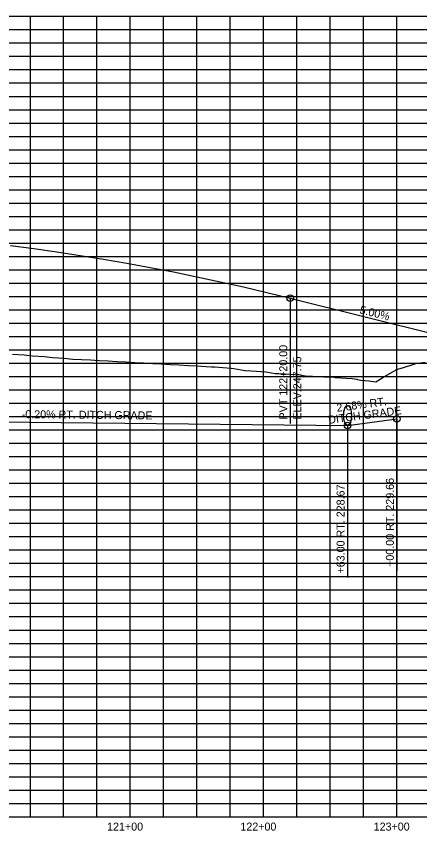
# Model space of a CAD drawing. Extents: x 921603 to 924670, y 1759276 to 1766491.
# Drawn here: x 923654 to 923957, y 1764922 to 1765532 of the extents above; entities that cross this region are included whole.
import ezdxf

# ---------------------------------------------------------------- set-up
doc = ezdxf.new("R2010")
doc.units = 0
for name, color, linetype in [('Level 8', 7, 'Continuous'), ('R_Axis_Annotation', 7, 'Continuous'), ('R_Exist Surface', 7, 'Continuous'), ('R_Grid', 7, 'Continuous'), ('R_Grid_Minor', 7, 'Continuous'), ('R_Vert Alg', 7, 'Continuous'), ('R_Vert Alg Annot', 7, 'Continuous')]:
    doc.layers.add(name, color=color, linetype=linetype)

msp = doc.modelspace()

# ---------------------------------------------------------------- linework, layer by layer
at = {"layer": 'Level 8'}
msp.add_ellipse((923902.83, 1765233.11), major_axis=(0, 7.5), ratio=0.4, dxfattribs=at)
at = {"layer": 'R_Exist Surface'}
msp.add_lwpolyline([(923651.49, 1765279.08), (923660.29, 1765278.47), (923666.55, 1765277.85), (923675.24, 1765277.26), (923681.59, 1765276.62), (923690.14, 1765276.05), (923696.6, 1765275.38), (923703.15, 1765274.99), (923709.89, 1765274.65), (923716.52, 1765274.26), (923723.19, 1765273.93), (923729.89, 1765273.53), (923736.48, 1765273.2), (923743.26, 1765272.79), (923749.77, 1765272.47), (923756.65, 1765272.05), (923763.06, 1765271.73), (923770.04, 1765271.31), (923776.35, 1765271), (923783.44, 1765270.57), (923789.64, 1765270.26), (923796.86, 1765269.82), (923800.71, 1765269.63), (923802.92, 1765269.52), (923809.14, 1765269.07), (923815.51, 1765268.59), (923817.58, 1765268.24), (923825.87, 1765266.8), (923826.02, 1765266.79), (923834.46, 1765266.26), (923841.63, 1765265.79), (923842.89, 1765265.58), (923848.62, 1765264.57), (923851.33, 1765264.43), (923859.77, 1765263.96), (923867.28, 1765263.51), (923868.2, 1765263.35), (923871.19, 1765262.8), (923876.64, 1765262.54), (923885.08, 1765262.1), (923892.45, 1765261.67), (923893.52, 1765261.46), (923893.58, 1765261.45), (923901.95, 1765261.09), (923906.31, 1765260.87), (923909.77, 1765260.28), (923910.39, 1765260.13), (923912.76, 1765259.58), (923918.83, 1765258.95), (923924.12, 1765258.36), (923927.27, 1765260.27), (923929.41, 1765261.55), (923935.7, 1765265.15), (923939.76, 1765267.44), (923943.72, 1765268.71), (923944.14, 1765268.84), (923952.58, 1765271.5), (923954.09, 1765271.97), (923961.01, 1765273.07)], dxfattribs=at)
at = {"layer": 'R_Grid'}
for p, q in [((921639.83, 1765532.26), (924639.83, 1765532.26)), ((921639.83, 1765532.26), (924639.83, 1765532.26)), ((923739.83, 1764932.26), (923739.83, 1765532.26)), ((923839.83, 1764932.26), (923839.83, 1765532.26)), ((923939.83, 1764932.26), (923939.83, 1765532.26)), ((921639.83, 1765482.26), (924639.83, 1765482.26)), ((921639.83, 1765432.26), (924639.83, 1765432.26)), ((921639.83, 1765382.26), (924639.83, 1765382.26)), ((921639.83, 1765332.26), (924639.83, 1765332.26)), ((921639.83, 1765282.26), (924639.83, 1765282.26)), ((921639.83, 1765232.26), (924639.83, 1765232.26)), ((921639.83, 1765182.26), (924639.83, 1765182.26)), ((921639.83, 1765132.26), (924639.83, 1765132.26)), ((921639.83, 1765082.26), (924639.83, 1765082.26)), ((921639.83, 1765032.26), (924639.83, 1765032.26)), ((921639.83, 1764982.26), (924639.83, 1764982.26)), ((921639.83, 1764932.26), (924639.83, 1764932.26))]:
    msp.add_line(p, q, dxfattribs=at)
at = {"layer": 'R_Grid_Minor'}
for p, q in [((923664.83, 1764932.26), (923664.83, 1765532.26)), ((923689.83, 1764932.26), (923689.83, 1765532.26)), ((923714.83, 1764932.26), (923714.83, 1765532.26)), ((923764.83, 1764932.26), (923764.83, 1765532.26)), ((923789.83, 1764932.26), (923789.83, 1765532.26)), ((923814.83, 1764932.26), (923814.83, 1765532.26)), ((923864.83, 1764932.26), (923864.83, 1765532.26)), ((923889.83, 1764932.26), (923889.83, 1765532.26)), ((923914.83, 1764932.26), (923914.83, 1765532.26)), ((921639.83, 1765522.26), (924639.83, 1765522.26)), ((921639.83, 1765512.26), (924639.83, 1765512.26)), ((921639.83, 1765502.26), (924639.83, 1765502.26)), ((921639.83, 1765492.26), (924639.83, 1765492.26)), ((921639.83, 1765472.26), (924639.83, 1765472.26)), ((921639.83, 1765462.26), (924639.83, 1765462.26)), ((921639.83, 1765452.26), (924639.83, 1765452.26)), ((921639.83, 1765442.26), (924639.83, 1765442.26)), ((921639.83, 1765422.26), (924639.83, 1765422.26)), ((921639.83, 1765412.26), (924639.83, 1765412.26)), ((921639.83, 1765402.26), (924639.83, 1765402.26)), ((921639.83, 1765392.26), (924639.83, 1765392.26)), ((921639.83, 1765372.26), (924639.83, 1765372.26)), ((921639.83, 1765362.26), (924639.83, 1765362.26)), ((921639.83, 1765352.26), (924639.83, 1765352.26)), ((921639.83, 1765342.26), (924639.83, 1765342.26)), ((921639.83, 1765322.26), (924639.83, 1765322.26)), ((921639.83, 1765312.26), (924639.83, 1765312.26)), ((921639.83, 1765302.26), (924639.83, 1765302.26)), ((921639.83, 1765292.26), (924639.83, 1765292.26)), ((921639.83, 1765272.26), (924639.83, 1765272.26)), ((921639.83, 1765262.26), (924639.83, 1765262.26)), ((921639.83, 1765252.26), (924639.83, 1765252.26)), ((921639.83, 1765242.26), (924639.83, 1765242.26)), ((921639.83, 1765222.26), (924639.83, 1765222.26)), ((921639.83, 1765212.26), (924639.83, 1765212.26)), ((921639.83, 1765202.26), (924639.83, 1765202.26)), ((921639.83, 1765192.26), (924639.83, 1765192.26)), ((921639.83, 1765172.26), (924639.83, 1765172.26)), ((921639.83, 1765162.26), (924639.83, 1765162.26)), ((921639.83, 1765152.26), (924639.83, 1765152.26)), ((921639.83, 1765142.26), (924639.83, 1765142.26)), ((921639.83, 1765122.26), (924639.83, 1765122.26)), ((921639.83, 1765112.26), (924639.83, 1765112.26)), ((921639.83, 1765102.26), (924639.83, 1765102.26)), ((921639.83, 1765092.26), (924639.83, 1765092.26)), ((921639.83, 1765072.26), (924639.83, 1765072.26)), ((921639.83, 1765062.26), (924639.83, 1765062.26)), ((921639.83, 1765052.26), (924639.83, 1765052.26)), ((921639.83, 1765042.26), (924639.83, 1765042.26)), ((921639.83, 1765022.26), (924639.83, 1765022.26)), ((921639.83, 1765012.26), (924639.83, 1765012.26)), ((921639.83, 1765002.26), (924639.83, 1765002.26)), ((921639.83, 1764992.26), (924639.83, 1764992.26)), ((921639.83, 1764972.26), (924639.83, 1764972.26)), ((921639.83, 1764962.26), (924639.83, 1764962.26)), ((921639.83, 1764952.26), (924639.83, 1764952.26)), ((921639.83, 1764942.26), (924639.83, 1764942.26))]:
    msp.add_line(p, q, dxfattribs=at)
at = {"layer": 'R_Vert Alg'}
for p, q in [((923859.83, 1765321.01), (923989.83, 1765288.51)), ((923544.83, 1765229.21), (923902.83, 1765225.61)), ((923902.83, 1765225.61), (923939.83, 1765230.56))]:
    msp.add_line(p, q, dxfattribs=at)
msp.add_lwpolyline([(923649.83, 1765360.38), (923667.33, 1765358.11), (923684.83, 1765355.64), (923702.33, 1765353), (923719.83, 1765350.18), (923737.33, 1765347.17), (923754.83, 1765343.98), (923772.33, 1765340.61), (923789.83, 1765337.05), (923807.33, 1765333.31), (923824.83, 1765329.39), (923842.33, 1765325.29), (923859.83, 1765321.01)], dxfattribs=at)
at = {"layer": 'R_Vert Alg Annot'}
for p, q in [((923859.83, 1765321.01), (923859.83, 1765311.01)), ((923859.83, 1765311.01), (923859.83, 1765227.01)), ((923939.83, 1765230.56), (923939.83, 1765200.56)), ((923902.83, 1765225.61), (923902.83, 1765195.61)), ((923902.83, 1765195.61), (923902.83, 1765111.61)), ((923939.83, 1765200.56), (923939.83, 1765116.56))]:
    msp.add_line(p, q, dxfattribs=at)
for centre in [(923859.83, 1765321.01), (923939.83, 1765230.56), (923902.83, 1765225.61)]:
    msp.add_circle(centre, 2.5, dxfattribs=at)

# ---------------------------------------------------------------- texts
at = {"layer": 'R_Axis_Annotation'}
for s, p in [('121+00', (923722.42, 1764921.91)), ('122+00', (923822.42, 1764921.91)), ('123+00', (923922.42, 1764921.91))]:
    msp.add_text(s, height=6, dxfattribs=at).set_placement(p)
at = {"layer": 'R_Vert Alg Annot'}
for s, rotation, p in [('-5.00%', 345.96376, (923908.89, 1765310.29)), ('PVT 122+20.00', 90, (923857.58, 1765230.01)), ('ELEV.247.75', 90, (923868.08, 1765230.01)), ('2.68% RT. ', 7.62, (923894.95, 1765235.78)), ('DITCH GRADE', 7.62, (923888.71, 1765226.75)), ('-0.20% RT. DITCH GRADE', 359.42386, (923658.36, 1765231.07)), ('+00.00 RT. 229.66', 90, (923937.58, 1765119.56)), ('+63.00 RT. 228.67', 90, (923900.58, 1765114.61))]:
    msp.add_text(s, height=6, rotation=rotation, dxfattribs=at).set_placement(p)

doc.saveas('drawing.dxf')
